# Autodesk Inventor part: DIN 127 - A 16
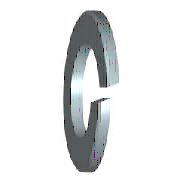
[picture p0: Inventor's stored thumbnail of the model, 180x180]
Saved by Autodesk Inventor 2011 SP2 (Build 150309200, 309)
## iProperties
Created: 2010-02
Part Number: DIN 127 - A 16
Material: Stahl, weich, unlegiert
Description: Federring
Document SubType Name: Modeling
Standard: DIN 127
Designer: JRE
Standards Organization: DIN
Language: de-DE
Size Designation: A 16
Categories: <MemberInstance><Categories><Category DisplayName="Verbindungselemente" InternalName="e4da775c-781d-43d5-af7c-5136215cf5a6" Mnemonic="FSTN"><Category DisplayNam
Density: 1 g/cm^3
IsCustomPart: 0
Author: JRE
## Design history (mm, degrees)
body "Solid1"
sketch "Skizze1"
  geometry: C1 r 13.7 at (0, 0); C2 r 8.5 at (0, 0); 1 further point
  constraints: 2 centre point, 2 coincident
  dimensions: "d0" = 17 diameter of C2 (= SD1); "d1" = 27.4 diameter of C1 (= SD2)
extrude "Körper" new body sketch "Skizze1" distance "d2" = 3.5 (= SD); taper "d3" = 0 deg
sketch "Skizze2"
  geometry: L1 (0, -8.5)-(0, 8.5) reference; L2 (3.5, 13.7)-(3.5, -13.7) reference; L3 (-1.2, 0)-(7.2, 0) reference; L4 (0, -0.7)-(3.5, 1.321); L5 (0, 0.7)-(3.5, 2.721)
  constraints: 4 end point, 4 point on line, 1 parallel
  dimensions: "d4" = 0.7 distance from line of L3 L4.start (= 0.2 x SD); "d5" = 0.7 distance from line of L3 L5.start (= 0.2 x SD); "d6" = 60 deg angle of L2 L4 (= FAWI)
extrude "Schnitt" cut sketch "Skizze2" stored distance "d7" = 3.5 (= SD); taper "d8" = 0 deg
workaxis "Work Axis1"
workplane "Work Plane1"
other parameters: "SD1" = 17 [user parameter; used in 1 equation term], "SD2" = 27.4 [user parameter; used in 1 equation term], "SD" = 3.5 [user parameter; used in 4 equation terms], "FAWI" = 60 deg [user parameter; used in 1 equation term], "d9" = 0, "d10" = 0, "d11" = 0, "d12" = 0, "NND" = 16 [user parameter]
